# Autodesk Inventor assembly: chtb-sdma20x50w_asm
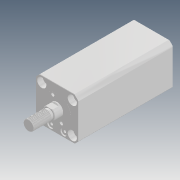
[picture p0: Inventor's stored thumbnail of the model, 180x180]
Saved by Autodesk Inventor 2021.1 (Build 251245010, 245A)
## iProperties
Company: Microsoft
Created: 2018-05
Part Number: chtb-sdma20x50w_asm
Description: STEP AP214
Document SubType Name: Assembly
Designer: user
Title: chtb-sdma20x50w_asm.STEP
Author: Windows
Revision Number: ÈÎºÎ
Sending System: SolidWorks 2015
Preprocessor: SwSTEP 2.0
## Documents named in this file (4)
- D:\Vault_2016\Projekty\Clamptek\Hydraulic\CHTB\CHTB-20\Inventor\CHTB-SDMA20x50W\chtb-sdma20x50w_asm.iam
- D:\Vault_2016\Projekty\Clamptek\Hydraulic\CHTB\CHTB-20\Inventor\CHTB-SDMA20x50W\CHTB-SDMA20X50NBT.ipt
- D:\Vault_2016\Projekty\Clamptek\Hydraulic\CHTB\CHTB-20\Inventor\CHTB-SDMA20x50W\CHTB-SDMA20X50WHSG.ipt
- D:\Vault_2016\Projekty\Clamptek\Hydraulic\CHTB\CHTB-20\Inventor\CHTB-SDMA20x50W\QG_3.ipt
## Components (3 placed, 3 different names)
1. CHTB-SDMA20X50NBT_1
2. CHTB-SDMA20X50WHSG_2
3. QG_3_3
